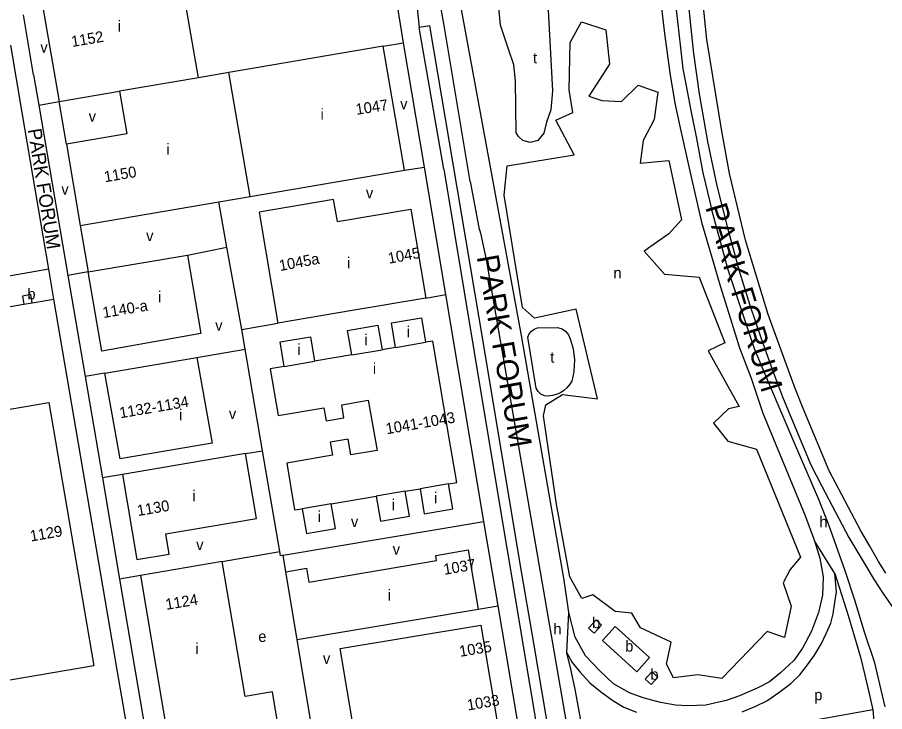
# Model space of a CAD drawing. Extents: x 154320 to 156262, y 382651 to 384180.
# Drawn here: x 154867.6 to 155184.2, y 383508.4 to 383761.9 of the extents above; entities that cross this region are included whole.
import ezdxf

# ---------------------------------------------------------------- set-up
doc = ezdxf.new("R2010")
doc.units = 0
for name, color, linetype in [('BLT_Basislijn', 7, 'Continuous'), ('BLT_Bebouwing', 7, 'Continuous'), ('BLT_Centroide', 7, 'Continuous'), ('BLT_Huisnummer', 7, 'Continuous'), ('BLT_Huisnummer_reeks', 7, 'Continuous'), ('BLT_Onderverdeling_panden', 7, 'Continuous'), ('BLT_Straatnaam', 7, 'Continuous'), ('BLT_Straatnaam_hoofdweg', 7, 'Continuous'), ('BLT_Vlakafsluiter', 7, 'Continuous')]:
    doc.layers.add(name, color=color, linetype=linetype)

msp = doc.modelspace()

# ---------------------------------------------------------------- linework, layer by layer
at = {"layer": 'BLT_Basislijn'}
for p, q in [((155008.64, 383752.61), (155006.35, 383766.23)), ((155013.57, 383765.24), (155014.36, 383758.12)), ((155023.31, 383706.47), (155014.36, 383758.12)), ((154869.35, 383727.19), (154865.28, 383751.73)), ((155001.21, 383751.34), (155008.64, 383752.61)), ((155016.26, 383707.16), (155008.64, 383752.61)), ((154873.59, 383740.95), (154875.5, 383729.82)), ((154875.5, 383729.82), (154882.87, 383731.11)), ((154875.5, 383729.82), (154886.09, 383667.66)), ((154885.53, 383715.54), (154882.87, 383731.11)), ((154879.13, 383669.91), (154869.35, 383727.19)), ((155008.93, 383706.03), (155016.26, 383707.16)), ((154944.1, 383677.97), (154941.15, 383694.48)), ((154890.57, 383685.9), (154893.54, 383668.92)), ((154929.79, 383675.09), (154944.1, 383677.97)), ((154949.62, 383647.96), (154944.1, 383677.97)), ((154879.13, 383669.91), (154791.23, 383654.83)), ((154880.99, 383658.99), (154879.13, 383669.91)), ((154893.54, 383668.92), (154886.09, 383667.66)), ((154886.09, 383667.66), (154892.37, 383630.77)), ((155016.79, 383659.41), (155024.06, 383660.67)), ((155037.97, 383577.79), (155024.06, 383660.67)), ((154873.07, 383657.65), (154880.99, 383658.99)), ((154949.62, 383647.96), (154962.76, 383650.23)), ((154950.86, 383640.7), (154949.62, 383647.96)), ((154933.19, 383637.68), (154950.86, 383640.7)), ((154957.18, 383603.67), (154950.86, 383640.7)), ((154899.6, 383632), (154892.37, 383630.77)), ((154892.37, 383630.77), (154898.69, 383593.7)), ((154950.87, 383602.6), (154957.18, 383603.67)), ((154963.47, 383566.81), (154957.18, 383603.67)), ((154905.97, 383594.94), (154898.69, 383593.7)), ((154898.69, 383593.7), (154904.98, 383556.75)), ((154942.46, 383563.23), (154963.47, 383566.81)), ((154912.56, 383558.14), (154904.98, 383556.75)), ((154904.98, 383556.75), (154919.23, 383473.09)), ((155035.83, 383545.81), (155043.13, 383547.03)), ((154976.53, 383494.14), (154969.79, 383534.71)), ((155179.9, 383509.09), (155180.25, 383504.95))]:
    msp.add_line(p, q, dxfattribs=at)
for points in [[(155068.93, 383544.59), (155067.27, 383556.4), (155051.69, 383645.7), (155029.25, 383767.38), (155028.07, 383780.37), (155027.84, 383789.11), (155027.13, 383799.74)], [(155100.53, 383800.01), (155100.87, 383786.51), (155101.99, 383771.63), (155103.88, 383756.04), (155105.77, 383741.63), (155107.66, 383730.52), (155109.55, 383721.54), (155113.09, 383705.71), (155117.34, 383687.05), (155121.59, 383672.64), (155124.19, 383663.9), (155127.97, 383651.85), (155131.28, 383641.22), (155135.53, 383630.11), (155139.78, 383617.35), (155155.13, 383580.26), (155158.67, 383570.81)], [(155184.62, 383558.94), (155182.02, 383563.2), (155178.83, 383568.75), (155175.52, 383574.42), (155163.95, 383596.27), (155154.5, 383619.07), (155151.2, 383627.34), (155141.75, 383653.45), (155133.49, 383680.5), (155127.58, 383704.83), (155124.75, 383720.31), (155119.32, 383753.74), (155116.84, 383777.6)], [(155112.11, 383770.87), (155114.47, 383748.66), (155116.48, 383733.9), (155119.55, 383716.53), (155122.98, 383700.35), (155126.99, 383684.52), (155131.12, 383669.28), (155135.02, 383656.76), (155139.15, 383644.59), (155143.29, 383633.01), (155146.95, 383623.32), (155151.44, 383612.46), (155157.22, 383598.52), (155161.24, 383590.72), (155166.31, 383581.27), (155171.15, 383571.94), (155176.94, 383562.25), (155180.37, 383556.46), (155183.55, 383551.62), (155187.45, 383546.07)], [(155107.86, 383766.75), (155108.84, 383758.32), (155109.96, 383748.5), (155110.58, 383743.12), (155111.78, 383736.87), (155113.51, 383727.91), (155115.5, 383717.59), (155117.79, 383705.69), (155118.02, 383704.61), (155120.36, 383694.5), (155121, 383691.73), (155123.32, 383683.25), (155125.87, 383673.88), (155126.89, 383670.14), (155129.3, 383662.89), (155132.81, 383652.3), (155136.57, 383640.95), (155141.38, 383629.68), (155147.03, 383616.31), (155151.25, 383606.48), (155155.51, 383596.7), (155160.02, 383585.91), (155163.86, 383576.35), (155169.72, 383559.92), (155173.18, 383549.2), (155176.88, 383537.22), (155180.44, 383526.65), (155184.25, 383510.12)], [(154873.59, 383740.95), (154869.83, 383762.84)], [(155028.35, 383699.05), (155018.21, 383758.77), (155014.36, 383758.12)], [(155032.93, 383701.93), (155023.39, 383758.91)], [(155024.06, 383660.67), (155016.26, 383707.16)], [(155023.31, 383706.47), (155038.2, 383616.87), (155062.68, 383469.79), (155069.36, 383428.11)], [(155051.11, 383563.15), (155037.8, 383642.75), (155028.35, 383699.05)], [(155036.13, 383685.14), (155036.76, 383683.03), (155038.71, 383673.47), (155078.78, 383441.91)], [(154793.03, 383644.07), (154870.05, 383657.16)], [(154903.62, 383526.48), (154903.13, 383529.37), (154880.99, 383658.99)], [(154964.66, 383565.48), (155037.97, 383577.79)], [(155043.13, 383547.03), (155037.97, 383577.79)], [(155158.67, 383570.81), (155160.56, 383564.43), (155161.74, 383557.58), (155161.5, 383550.97), (155160.09, 383544.59), (155157.49, 383537.74), (155154.18, 383531.59), (155151.11, 383527.1), (155146.15, 383522.62), (155142.14, 383519.31), (155137.65, 383516.95), (155131.27, 383514.11), (155126.32, 383512.46), (155118.99, 383510.8), (155112.38, 383510.57), (155107.89, 383510.8), (155102.46, 383511.75), (155096.09, 383513.4), (155091.13, 383515.29), (155085.22, 383518.6), (155080.26, 383523.32), (155075.07, 383528.76), (155071.29, 383535.61), (155068.93, 383544.59)], [(154964.66, 383565.48), (154963.72, 383565.34), (154963.47, 383566.81)], [(154965.67, 383559.47), (154964.66, 383565.48)], [(155048.57, 383212.61), (155056.82, 383221.58), (155062.17, 383228.69), (155068.4, 383238.67), (155073.45, 383249.51), (155077.96, 383263.67), (155080.28, 383275.23), (155081.04, 383286.89), (155081.1, 383302.07), (155080.89, 383320.08), (155079.8, 383347.13), (155078.77, 383362.31), (155076.55, 383392.27), (155074.59, 383416.48), (155071.13, 383443.2), (155067.82, 383464.17), (155063.32, 383490.92), (155056.28, 383532.64), (155051.11, 383563.15)], [(155132.19, 383508.38), (155137.15, 383510.39), (155141.16, 383512.4), (155145.65, 383515.35), (155150.02, 383518.66), (155153.21, 383521.85), (155156.4, 383525.98), (155158.64, 383529.05), (155161.12, 383533.31), (155162.89, 383536.97), (155164.54, 383540.75), (155165.49, 383544.06), (155166.08, 383548.19), (155166.67, 383552.09), (155166.08, 383558.82)], [(155166.08, 383558.82), (155171.04, 383543.11), (155175.41, 383528.34), (155178.24, 383516.65), (155179.9, 383509.09)], [(155054.06, 383481.93), (155045.91, 383530.45), (155043.13, 383547.03)], [(155068.19, 383529.88), (155070.19, 383526.34), (155072.91, 383522.91), (155076.57, 383518.89), (155080.47, 383515.7), (155084.95, 383512.51), (155088.97, 383510.03), (155093.69, 383508.26)], [(155075.98, 383490.54), (155072.91, 383507.2), (155071.26, 383516.65), (155069.72, 383523.86), (155068.19, 383529.88)], [(154909.63, 383491.26), (154903.62, 383526.48)], [(155179.9, 383509.09), (155159.58, 383505.43), (155131.48, 383499.99), (155099.48, 383494.44), (155075.98, 383490.54)]]:
    msp.add_lwpolyline(points, dxfattribs=at)
for points in [[(155044.98, 383766.92), (155056.08, 383768.18), (155058.98, 383767.31), (155061.38, 383764.56), (155062.99, 383734.99), (155062.37, 383728.13), (155060.83, 383723.61), (155059.83, 383719.63), (155057.57, 383716.89), (155054.85, 383716.24), (155052.13, 383716.92), (155050.54, 383718.36), (155049.71, 383719.73), (155049.52, 383738.66), (155048.85, 383744.58), (155046.77, 383750.57), (155044.03, 383759), (155043.48, 383764.04), (155043.76, 383765.69)], [(155070.86, 383711.67), (155064.16, 383724.3), (155070.39, 383727.15), (155069.04, 383735.41), (155069.44, 383752.74), (155073.56, 383760.23), (155082.5, 383757.35), (155083.76, 383744.75), (155076.22, 383733.11), (155080.97, 383731.57), (155088.12, 383731.16), (155094.23, 383737.07), (155101.44, 383734.51), (155100.13, 383724.58), (155096.03, 383716.86), (155094.98, 383708.6), (155105.48, 383709.65), (155110.09, 383687.94), (155105.49, 383682.8), (155096.42, 383676.47), (155103.82, 383668.06), (155116.55, 383667.08), (155125.89, 383643.02), (155119.75, 383640.12), (155131.06, 383619.84), (155127.18, 383619), (155121.79, 383613.69), (155126.99, 383607.14), (155137.5, 383604.2), (155153.45, 383564.82), (155149.79, 383560.34), (155147.2, 383555.37), (155150.12, 383546.85), (155147.67, 383535.52), (155141.29, 383537.62), (155124.81, 383520.48), (155116, 383521.81), (155107.11, 383520.76), (155104.63, 383525.75), (155106.24, 383533.73), (155095.07, 383538.97), (155091.94, 383544.4), (155085.84, 383544.94), (155077.75, 383551.03), (155073.71, 383549.69), (155069.25, 383557.61), (155064.41, 383584.11), (155059.74, 383616.4), (155060.56, 383620.43), (155066.61, 383624.13), (155079.41, 383622.66), (155071.64, 383655.31), (155056.4, 383652.05), (155052.04, 383656), (155045.29, 383696.9), (155046.49, 383707.7)], [(155056.76, 383627.94), (155053.96, 383645.15), (155054.52, 383646.33), (155055.29, 383647.28), (155056.32, 383648.05), (155057.46, 383648.54), (155064.86, 383648.7), (155066.48, 383648.17), (155067.76, 383647.29), (155068.81, 383645.99), (155069.42, 383644.51), (155070.5, 383640.89), (155071.01, 383636.81), (155070.78, 383632.48), (155069.99, 383629.01), (155069.32, 383627.9), (155068.25, 383626.62), (155067.15, 383625.65), (155065.86, 383624.82), (155064.37, 383624.16), (155062.98, 383623.78), (155061.44, 383623.6), (155060.09, 383623.64), (155058.75, 383624.31), (155057.75, 383625.27), (155057.08, 383626.45)]]:
    msp.add_lwpolyline(points, close=True, dxfattribs=at)
at = {"layer": 'BLT_Bebouwing'}
for p, q in [((154933.72, 383739.79), (154925.95, 383785.34)), ((154875.1, 383776.59), (154882.87, 383731.11)), ((155001.21, 383751.34), (154944.88, 383741.74)), ((154882.87, 383731.11), (154904.98, 383734.88)), ((154952.61, 383696.43), (155008.93, 383706.03)), ((154984.48, 383687.3), (155011.24, 383691.88)), ((155011.24, 383691.88), (155016.79, 383659.41)), ((154893.54, 383668.92), (154929.79, 383675.09)), ((154929.79, 383675.09), (154934.66, 383646.4)), ((154898.46, 383640.06), (154893.54, 383668.92)), ((155016.79, 383659.41), (154989.9, 383654.82)), ((154989.9, 383654.82), (154962.76, 383650.23)), ((154934.66, 383646.4), (154898.46, 383640.06)), ((155019.3, 383643.69), (155016.64, 383643.23)), ((155025.24, 383608.19), (155019.3, 383643.69)), ((155005.66, 383641.36), (155000.79, 383640.53)), ((154899.6, 383632), (154933.19, 383637.68)), ((154933.19, 383637.68), (154938.76, 383606.43)), ((154989.77, 383638.65), (154976.08, 383636.32)), ((154905.23, 383600.72), (154899.6, 383632)), ((154879.18, 383621.21), (154895.55, 383525.11)), ((154938.76, 383606.43), (154905.23, 383600.72)), ((154950.87, 383602.6), (154905.97, 383594.94)), ((155009.23, 383588.84), (155014.62, 383589.75)), ((154982.2, 383584.29), (154998.67, 383587.06)), ((154942.46, 383563.23), (154912.56, 383558.14)), ((154912.56, 383558.14), (154924.85, 383485.44)), ((154969.79, 383534.71), (155035.83, 383545.81)), ((154985.47, 383531.41), (155036.82, 383540.02)), ((155036.82, 383540.02), (155046.76, 383480.84)), ((154995.44, 383472.21), (154985.47, 383531.41))]:
    msp.add_line(p, q, dxfattribs=at)
for points in [[(155008.93, 383706.03), (155001.21, 383751.34)], [(154944.88, 383741.74), (154944.88, 383741.74), (154933.72, 383739.79)], [(154904.98, 383734.88), (154907.63, 383719.32), (154885.53, 383715.54)], [(154885.53, 383715.54), (154890.57, 383685.9)], [(154890.57, 383685.9), (154941.15, 383694.48)], [(154941.15, 383694.48), (154952.61, 383696.43)], [(154984.48, 383687.3), (154983.1, 383695.38), (154955.86, 383690.71), (154962.76, 383650.23)], [(154873.07, 383657.65), (154872.55, 383660.65), (154869.54, 383660.13), (154870.05, 383657.16)], [(154870.05, 383657.16), (154873.07, 383657.65)], [(155005.66, 383641.36), (155004.17, 383650.32), (155015.15, 383652.18), (155016.64, 383643.23)], [(154989.77, 383638.65), (154988.21, 383647.6), (154999.23, 383649.48), (155000.79, 383640.53)], [(154965.09, 383634.45), (154963.6, 383643.42), (154974.59, 383645.29), (154976.08, 383636.32)], [(154965.09, 383634.45), (154959.94, 383633.57), (154962.85, 383616.51), (154979.57, 383619.36), (154980.37, 383614.53), (154986.86, 383615.62), (154986.05, 383620.46), (154995.75, 383622.1), (154999, 383603.75)], [(154796.3, 383624.97), (154807.03, 383626.73), (154809.97, 383609.47), (154879.18, 383621.21)], [(154999, 383603.75), (154989.34, 383602.11), (154988.34, 383607.92), (154981.86, 383606.81), (154982.68, 383602.01), (154965.97, 383599.17), (154968.86, 383582.04), (154971.63, 383582.5)], [(155025.07, 383591.51), (155028.11, 383592.03), (155025.24, 383608.19)], [(154905.97, 383594.94), (154911.27, 383563.9), (154923.09, 383565.9), (154921.83, 383573.32), (154954.9, 383578.91), (154950.87, 383602.6)], [(155014.62, 383589.75), (155016.15, 383580.67), (155026.61, 383582.43), (155025.07, 383591.51)], [(154998.67, 383587.06), (155000.2, 383577.98), (155010.76, 383579.76), (155009.23, 383588.84)], [(154971.63, 383582.5), (154973.16, 383573.42), (154983.73, 383575.2), (154982.2, 383584.29)], [(154965.67, 383559.47), (154973.19, 383560.73), (154974, 383555.72), (155020.69, 383563.54), (155020.36, 383565.45), (155032.17, 383567.44), (155035.83, 383545.81)], [(154964.69, 383492.17), (154960.72, 383515.62), (154950.86, 383513.94), (154942.46, 383563.23)], [(154969.79, 383534.71), (154965.67, 383559.47)], [(154895.55, 383525.11), (154815.63, 383511.49)]]:
    msp.add_lwpolyline(points, dxfattribs=at)
for points in [[(155078.88, 383541.86), (155076.15, 383538.88), (155078.18, 383537.03), (155080.9, 383540.01)], [(155081.18, 383534.36), (155085.86, 383539.53), (155098.43, 383528.13), (155093.75, 383522.96)], [(155096.79, 383520.3), (155098.99, 383518.3), (155101.4, 383520.95), (155099.2, 383522.95)]]:
    msp.add_lwpolyline(points, close=True, dxfattribs=at)
at = {"layer": 'BLT_Onderverdeling_panden'}
for p, q in [((154952.61, 383696.43), (154944.88, 383741.74)), ((154933.72, 383739.79), (154904.98, 383734.88)), ((154989.77, 383638.65), (155000.79, 383640.53)), ((155005.66, 383641.36), (155016.64, 383643.23)), ((154965.09, 383634.45), (154976.08, 383636.32)), ((155025.07, 383591.51), (155014.62, 383589.75)), ((155009.23, 383588.84), (154998.67, 383587.06)), ((154982.2, 383584.29), (154971.63, 383582.5))]:
    msp.add_line(p, q, dxfattribs=at)
at = {"layer": 'BLT_Vlakafsluiter'}
for p, q in [((155023.39, 383758.91), (155020.28, 383776.36)), ((155032.93, 383701.93), (155036.13, 383685.14)), ((155166.08, 383558.82), (155158.67, 383570.81)), ((155068.19, 383529.88), (155068.93, 383544.59))]:
    msp.add_line(p, q, dxfattribs=at)

# ---------------------------------------------------------------- texts
at = {"layer": 'BLT_Centroide'}
for s, p in [('i', (154904.27, 383756.7)), ('t', (155055.88, 383745.08)), ('i', (154978.32, 383724.51)), ('i', (154922.08, 383711.75)), ('i', (154988.02, 383670.25)), ('n', (155085.24, 383666.59)), ('b', (154871.3, 383658.9)), ('i', (154918.98, 383657.84)), ('i', (155009.73, 383645.11)), ('i', (154994.35, 383642.18)), ('i', (154969.82, 383638.63)), ('t', (155062.16, 383635.78)), ('i', (154997.42, 383631.71)), ('i', (154926.7, 383614.81)), ('i', (154931.57, 383585.23)), ('i', (155019.75, 383584.45)), ('i', (155004.29, 383581.95)), ('i', (154977.25, 383577.63)), ('v', (154989.41, 383575.77)), ('h', (155160.42, 383575.68)), ('i', (155002.79, 383548.97)), ('h', (155063.32, 383536.6)), ('e', (154955.6, 383533.86)), ('i', (154932.62, 383529.46)), ('p', (155158.53, 383512.54))]:
    msp.add_text(s, height=4, dxfattribs=at).set_placement(p)
for s, p in [('v', (154876.03, 383749)), ('v', (155007.36, 383728.31)), ('v', (154893.66, 383723.8)), ('v', (154883.68, 383697.17)), ('v', (154994.87, 383695.85)), ('v', (154914.64, 383680.18)), ('v', (154939.84, 383647.48)), ('v', (154944.84, 383615.21)), ('v', (154932.9, 383567.38)), ('v', (155004.64, 383565.75)), ('b', (155077.43, 383538.88)), ('b', (155089.51, 383530.32)), ('v', (154979.17, 383525.86)), ('b', (155098.7, 383520.02))]:
    msp.add_text(s, height=4, rotation=359.5, dxfattribs=at).set_placement(p)
at = {"layer": 'BLT_Huisnummer'}
for s, rotation, p in [('1152', 9.6197, (154887.66, 383751.03)), ('1047', 8.6623, (154991.44, 383726.26)), ('1150', 9.6197, (154899.64, 383701.65)), ('1130', 9.6197, (154911.68, 383579.78)), ('1129', 9.7394, (154872.6, 383570.49)), ('1037', 9.6197, (155023.52, 383558.32))]:
    msp.add_text(s, height=4, rotation=rotation, dxfattribs=at).set_placement(p)
at = {"layer": 'BLT_Huisnummer_reeks'}
for s, rotation, p in [('1045a', 10.6623, (154963.55, 383669.23)), ('1045', 10.6623, (155003.29, 383671.89)), ('1140-a', 9.6197, (154899.08, 383652.07)), ('1132-1134', 9.6197, (154905.24, 383615.48)), ('1041-1043', 9.7394, (155002.46, 383609.65)), ('1124', 9.6197, (154922.06, 383545.53)), ('1035', 9.5294, (155029.29, 383528.38)), ('1033', 9.5294, (155032.13, 383508.79))]:
    msp.add_text(s, height=4, rotation=rotation, dxfattribs=at).set_placement(p)
at = {"layer": 'BLT_Straatnaam'}
msp.add_text('PARK FORUM', height=5, rotation=279.1888, dxfattribs=at).set_placement((154871.41, 383720.91))
at = {"layer": 'BLT_Straatnaam_hoofdweg'}
for rotation, p in [(287, (155118.67, 383692.6)), (280, (155035.3, 383674.51))]:
    msp.add_text('PARK FORUM', height=8, rotation=rotation, dxfattribs=at).set_placement(p)

doc.saveas('drawing.dxf')
